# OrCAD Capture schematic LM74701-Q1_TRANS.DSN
size D; title: LM74701-Q1: Low IQ Reverse Battery Protection Ideal Diode; rev: 1.0; note: Datasheet: SNOSDB8    EVM: PSIL136; note: Controller with Integrated VDS Clamp
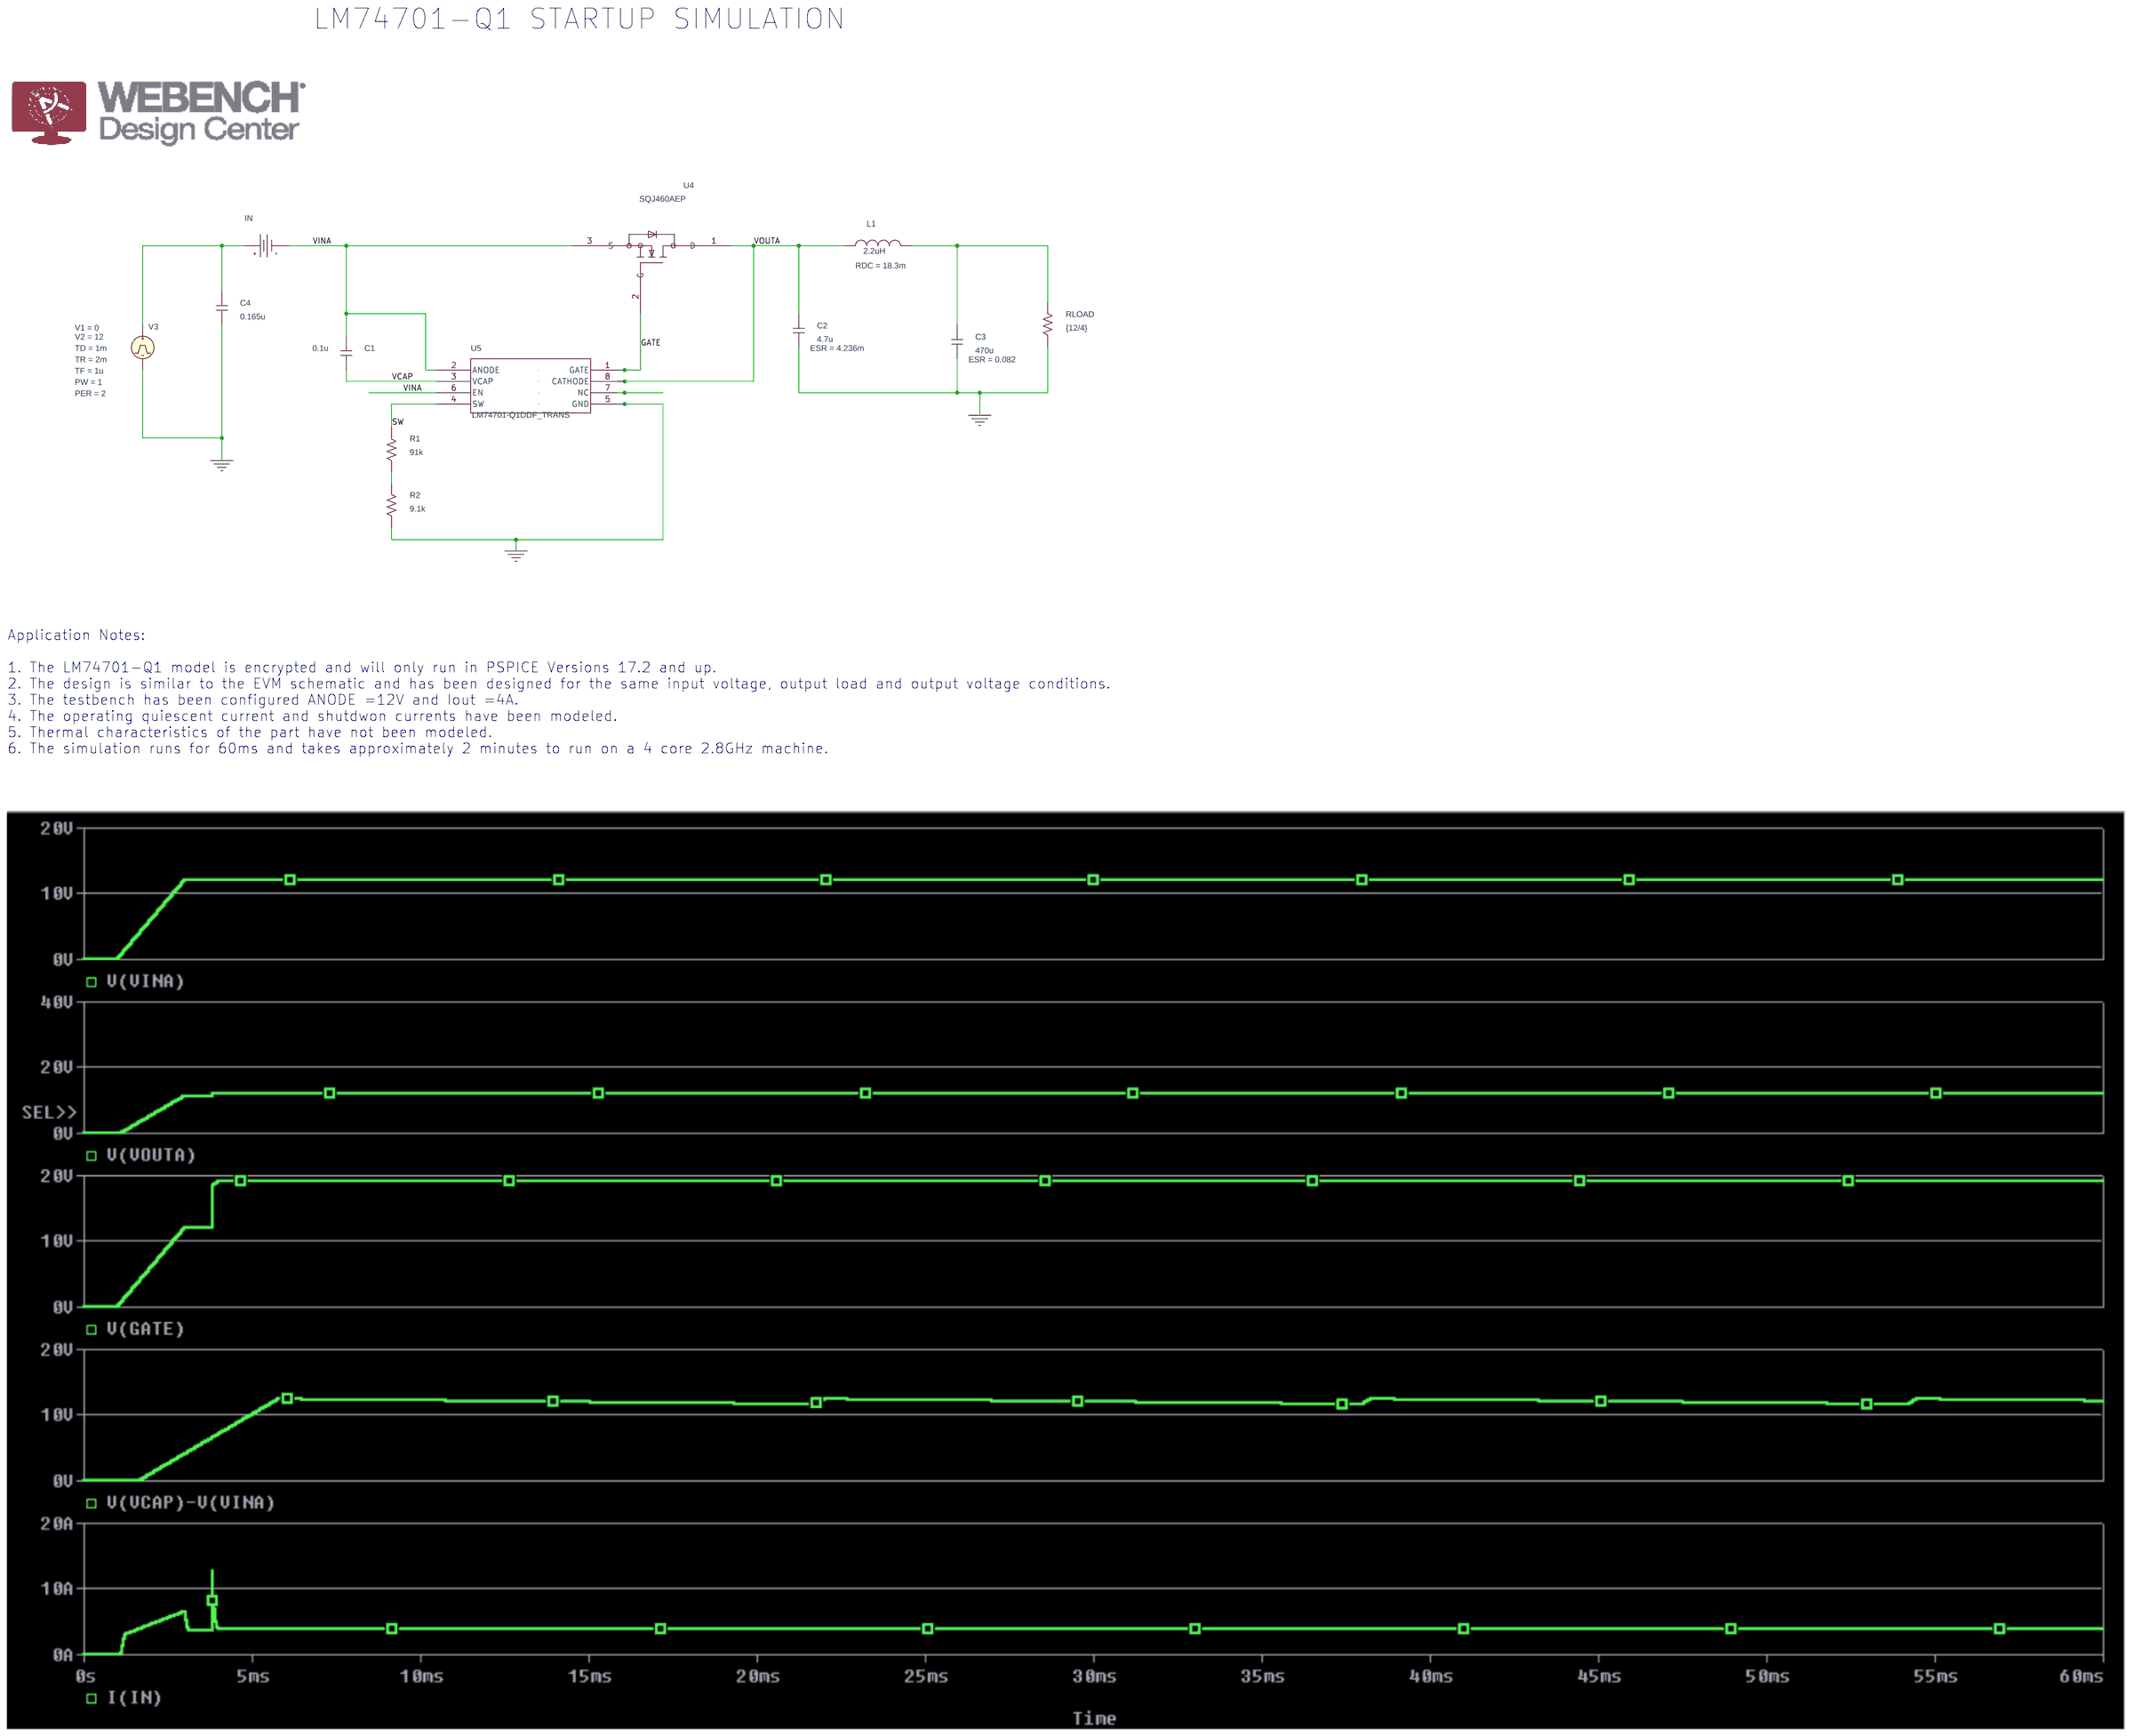
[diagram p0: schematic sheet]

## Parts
C1  0.1u  [RAD/CK05]
C2  4.7u  [RAD/CK05]
C3  470u  [RAD/CK05]
C4  0.165u  [RAD/CK05]
IN  VDC
L1  2.2uH  [DISC/.350x.175/LS.200x.100/.034]
R1  91k  [AX/RC05]
R2  9.1k  [AX/RC05]
RLOAD  {12/4}  [AX/RC05]
U4  SQJ460AEP
U5  LM74701-Q1DDF_TRANS  [DDF0008A-IPC_A]
V3  VPULSE

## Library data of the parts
C1 C4 = C
C2 = C: AppProp: InductiveSlave:;SRF:;PrevCap:220u;PrevESL:; ESR: 4.236m
C3 = C: AppProp: InductiveSlave:;SRF:;PrevCap:220u;PrevESL:; ESR: 0.082
IN = VDC
L1 = L: AppProp: SRF:; RDC: 18.3m
R1 R2 RLOAD = R
U4 = SQJ460AEP
U5 = LM74701-Q1DDF_TRANS
V3 = VPULSE: PER: 2; PW: 1; TD: 1m; TF: 1u; TR: 2m; V1: 0; V2: 12

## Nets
VINA: C1.1 IN.1(-) U4.3(S) U5.2(ANODE) U5.6(EN)
0: C2.1 C3.1 C4.2 R2.1 RLOAD.1 U5.5(GND) V3.2(-)
GATE: U4.2(G) U5.1(GATE)
SW: R1.1 U5.4(SW)
VCAP: C1.2 U5.3(VCAP)
VOUTA: C2.2 L1.1 U4.1(D) U5.8(CATHODE)
N16518432: C4.1 IN.0(+) V3.1(+)
N16540063: C3.2 L1.2 RLOAD.2
N16540365: R1.2 R2.2

Not connected (* = marked no-connect by the designer): U5 7(NC)

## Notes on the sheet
- LM74701-Q1 STARTUP SIMULATION
- Application Notes:
  1. The LM74701-Q1 model is encrypted and will only run in PSPICE Versions 17.2 and up.
  2. The design is similar to the EVM schematic and has been designed for the same input voltage, output load and output voltage conditions.
  3. The testbench has been configured ANODE =12V and Iout =4A.
  4. The operating quiescent current and shutdwon currents have been modeled.
  5. Thermal characteristics of the part have not been modeled.
  6. The simulation runs for 60ms and takes approximately 2 minutes to run on a 4 core 2.8GHz machine.
